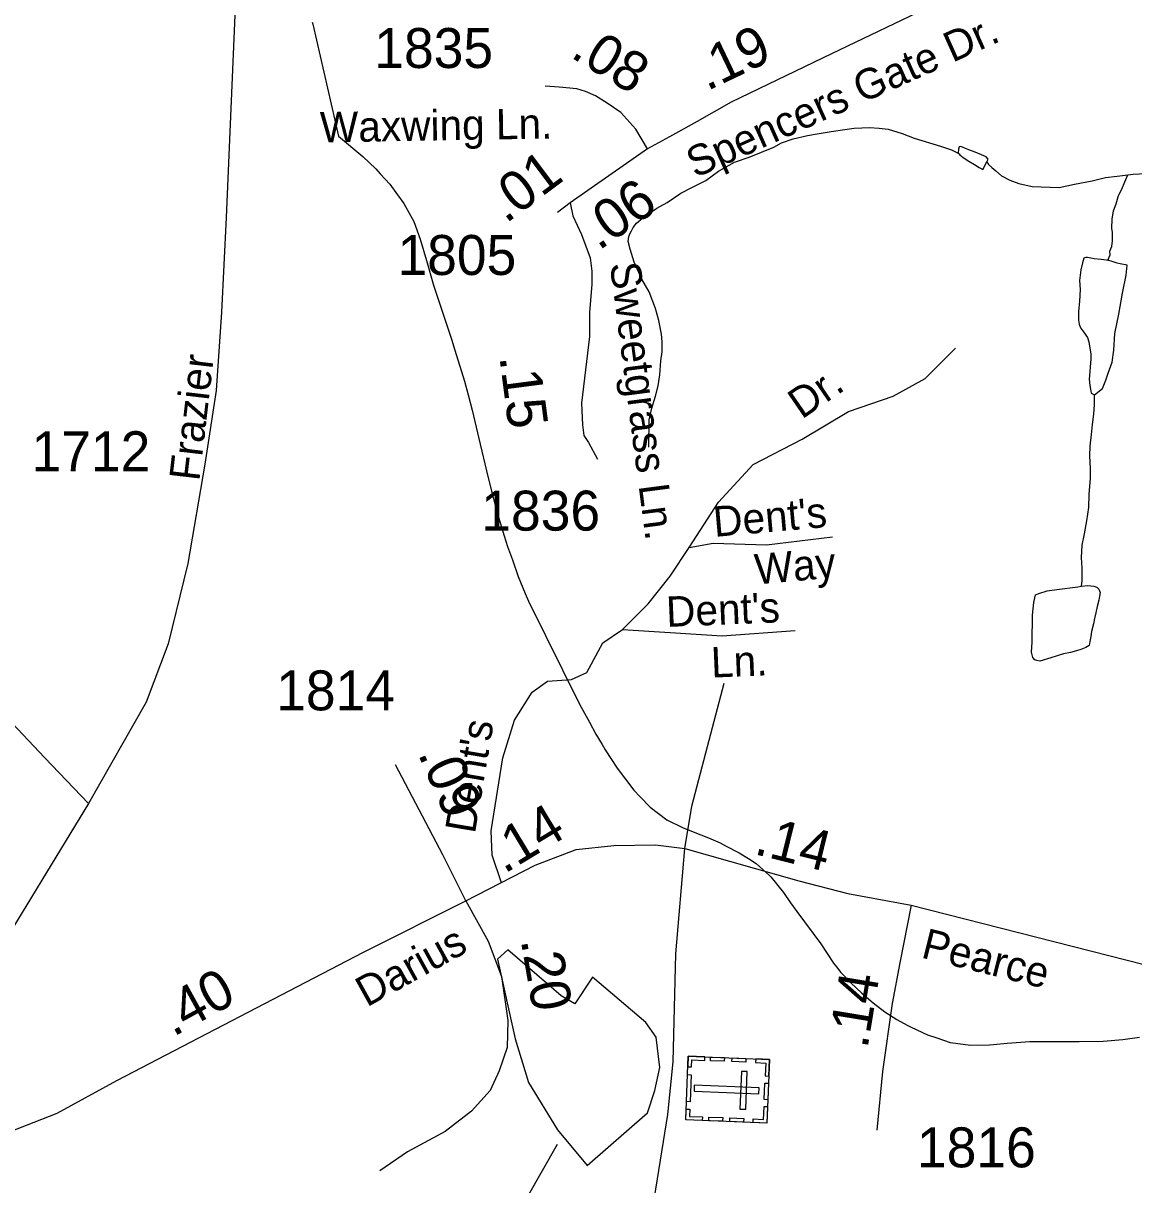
# Model space of a CAD drawing. Extents: x 2126262 to 2293712, y 749403 to 919119.
# Drawn here: x 2183876 to 2187352, y 801398 to 805032 of the extents above; entities that cross this region are included whole.
import ezdxf

# ---------------------------------------------------------------- set-up
doc = ezdxf.new("R2010")
doc.units = 0
for name, color, linetype in [('Exist Cultural Cemetery CELL', 7, 'Continuous'), ('Exist Hydrographic Misc Water Feature', 7, 'Continuous'), ('Exist Road Non-System Type 51', 7, 'Continuous'), ('Exist Road Non-System Type 51 Label', 7, 'Continuous'), ('Exist Road Secondary Mileage Hundredths English Label', 7, 'Continuous'), ('Exist Road Secondary Type 51 Attributed', 7, 'Continuous'), ('Exist Road Secondary Type 51 Label', 7, 'Continuous'), ('Exist Road Secondary Type 51 Number Label', 7, 'Continuous')]:
    doc.layers.add(name, color=color, linetype=linetype)

msp = doc.modelspace()

# ---------------------------------------------------------------- linework, layer by layer
at = {"layer": 'Exist Cultural Cemetery CELL'}
for points in [[(2186212.1, 801789.6), (2186203.9, 801590.6), (2185949.5, 801601.1), (2185957.7, 801800.1)], [(2185956.4, 801767), (2185967.9, 801766.5), (2185968.8, 801788.5), (2186009.1, 801786.9), (2186009.6, 801798), (2185957.7, 801800.1)], [(2186027.6, 801797.2), (2186070.9, 801795.4), (2186070.4, 801784), (2186027.1, 801785.8)], [(2186094.7, 801794.4), (2186138, 801792.6), (2186137.5, 801781.3), (2186094.3, 801783)], [(2186168.8, 801791.3), (2186168.4, 801780), (2186200.5, 801778.7), (2186198.8, 801738.2), (2186210, 801737.7), (2186212.1, 801789.6)], [(2186142.4, 801751.6), (2186123.8, 801752.4), (2186118.9, 801634.7), (2186137.6, 801633.9)], [(2185966.8, 801742.2), (2185963.3, 801657.4), (2185951.9, 801657.9), (2185955.4, 801742.6)], [(2186209, 801715.6), (2186206.9, 801663.8), (2186195.5, 801664.2), (2186197.6, 801716)], [(2186178.3, 801681.8), (2186179.1, 801700.5), (2185976.5, 801708.9), (2185975.7, 801690.2)], [(2186160.6, 801592.4), (2186161, 801603.7), (2186193.2, 801602.4), (2186194.9, 801642.9), (2186206, 801642.4), (2186203.8, 801590.6)], [(2185950.9, 801634.2), (2185962.3, 801633.8), (2185961.4, 801611.8), (2186001.8, 801610.1), (2186001.3, 801599), (2185949.5, 801601.1)], [(2186022.2, 801609.5), (2186065.4, 801607.7), (2186065, 801596.4), (2186021.7, 801598.1)], [(2186088, 801606.8), (2186131.3, 801605), (2186130.8, 801593.6), (2186087.6, 801595.4)]]:
    msp.add_lwpolyline(points, close=True, dxfattribs=at)
at = {"layer": 'Exist Hydrographic Misc Water Feature'}
for p, q in [((2184780.9, 805035), (2184782.2, 805029.1)), ((2185216.1, 804043.7), (2185227.3, 804009.3)), ((2186211.6, 802365.4), (2186216.3, 802361.2)), ((2186900.2, 801835.5), (2186912.5, 801836.7)), ((2187318, 801852.2), (2187370.1, 801859.2))]:
    msp.add_line(p, q, dxfattribs=at)
for points in [[(2184782.2, 805029.1), (2184863.2, 804678.3), (2184939.2, 804615.3), (2184979.2, 804576.3), (2184993.6, 804560.6)], [(2184782.2, 805029.1), (2184863.2, 804678.3), (2184939.2, 804615.3), (2184979.2, 804576.3), (2184993.6, 804560.6)], [(2185834.3, 803705.4), (2185834.1, 803733.4), (2185835.7, 803767.4), (2185835.7, 803791.4), (2185843.5, 803827.5), (2185855.2, 803865.5), (2185863, 803897.5), (2185868.7, 803931.6), (2185872.2, 803975.6), (2185876.3, 804003.6), (2185875.9, 804035.6), (2185873.7, 804059.6), (2185865.5, 804101.5), (2185855.2, 804139.4), (2185834.9, 804191.3), (2185812.6, 804231.1), (2185788.4, 804284.9), (2185776.1, 804324.8), (2185769.7, 804348.8), (2185771.8, 804364.8), (2185775.9, 804374.8), (2185779.5, 804382.9), (2185785.5, 804392.9), (2185795.5, 804406.9), (2185815.2, 804423.1), (2185835.3, 804437.2), (2185859.1, 804453.4), (2185891.1, 804471.6), (2185934.8, 804499.9), (2185968.6, 804518.1), (2186012.5, 804540.4), (2186052.3, 804568.7), (2186102.1, 804597), (2186148, 804613.3), (2186225.7, 804643.8), (2186249.5, 804658), (2186285.6, 804670.3), (2186331.3, 804680.6), (2186367.2, 804686.8), (2186405.4, 804693.1), (2186447.2, 804699.4), (2186477.3, 804703.6), (2186525.3, 804705.9), (2186555.3, 804704), (2186583.3, 804700.3), (2186627.2, 804686.6), (2186665.2, 804672.9), (2186747.6, 804647.4), (2186781.4, 804635.7), (2186802.3, 804625.3), (2186805.4, 804623.8)], [(2186891.7, 804598.4), (2186893.8, 804602.4), (2186895.8, 804606.4), (2186889.7, 804614.4), (2186875.5, 804620.3), (2186855.5, 804628.2), (2186835.6, 804636.1), (2186825.5, 804640), (2186815.5, 804643.9), (2186809.5, 804645.9), (2186805.4, 804645.8), (2186803.6, 804637.8), (2186802.3, 804625.3), (2186805.4, 804623.8)], [(2186805.4, 804623.8), (2186807.7, 804619.9), (2186817.7, 804611.9), (2186835.8, 804600.1), (2186853.8, 804590.2), (2186868, 804580.3), (2186876, 804576.3), (2186880.1, 804574.4), (2186891.7, 804598.4)], [(2186891.7, 804598.4), (2186897.7, 804590.5), (2186907.7, 804580.5), (2186920, 804570.6), (2186938.1, 804554.8), (2186963.9, 804540.9), (2186992.2, 804531.1), (2187034.3, 804521.4), (2187118.3, 804518), (2187166.3, 804528.4), (2187222.1, 804538.8), (2187263.9, 804549), (2187300, 804553.3), (2187334, 804557.5)], [(2184993.6, 804560.6), (2185023.3, 804528.1), (2185047.5, 804495.1)], [(2184993.6, 804560.6), (2185023.3, 804528.1), (2185047.5, 804495.1)], [(2187273.8, 804289.2), (2187271.7, 804293.1), (2187277.9, 804307.2), (2187277.4, 804319.2), (2187283.6, 804333.3), (2187285.2, 804351.2), (2187285.2, 804377.2), (2187283, 804391.2), (2187284.8, 804419.2), (2187288.7, 804445.3), (2187296.5, 804467.3), (2187304.3, 804493.3), (2187314.4, 804513.4), (2187324, 804535.4), (2187334, 804557.5)], [(2187334, 804557.5), (2187349.8, 804559.6), (2187389.8, 804561.9)], [(2185047.5, 804495.1), (2185067, 804468.4), (2185098.4, 804411.4), (2185118.3, 804356.7), (2185137.9, 804289.4)], [(2185047.5, 804495.1), (2185067, 804468.4), (2185098.4, 804411.4), (2185118.3, 804356.7), (2185137.9, 804289.4)], [(2187273.8, 804289.2), (2187249.8, 804293), (2187227.8, 804294.9), (2187207.7, 804298.7), (2187201.8, 804298.7), (2187195.8, 804296.6), (2187191.7, 804282.6), (2187186, 804260.6), (2187182.3, 804226.6), (2187184.6, 804198.5), (2187182.7, 804162.5), (2187179, 804128.6), (2187179, 804102.6), (2187181.3, 804090.6), (2187185.2, 804078.6), (2187195.2, 804066.7), (2187207.5, 804048.8), (2187211.4, 804034.8), (2187217.8, 803996.9), (2187218, 803980.9), (2187215.9, 803956.9), (2187214.3, 803942.9), (2187212.2, 803918.8), (2187214.5, 803898.8), (2187216.5, 803886.9), (2187218.8, 803874.9), (2187228.9, 803869)], [(2185137.9, 804289.4), (2185160.3, 804212.1), (2185216.1, 804043.7)], [(2185137.9, 804289.4), (2185160.3, 804212.1), (2185216.1, 804043.7)], [(2187228.9, 803869), (2187254.5, 803889.2), (2187264.3, 803915.3), (2187272.3, 803937.2), (2187284, 803971.4), (2187289.8, 804009.4), (2187293.2, 804061.4), (2187304.9, 804121.4), (2187316.4, 804187.5), (2187328.1, 804243.5), (2187331.8, 804275.6), (2187309.8, 804279.4), (2187299.8, 804281.4), (2187281.8, 804287.3), (2187273.8, 804289.2)], [(2185227.3, 804009.3), (2185257.5, 803911.8), (2185268.8, 803868.9)], [(2185227.3, 804009.3), (2185257.5, 803911.8), (2185268.8, 803868.9)], [(2185268.8, 803868.9), (2185281.3, 803821.9), (2185306.1, 803714.5)], [(2185268.8, 803868.9), (2185281.3, 803821.9), (2185306.1, 803714.5)], [(2187188.7, 803270.9), (2187190.7, 803288.9), (2187190.5, 803326.9), (2187188.3, 803360.8), (2187190.1, 803398.9), (2187197.7, 803434.9), (2187205.5, 803474.9), (2187211, 803517), (2187212.7, 803557), (2187216.5, 803609), (2187216.3, 803639), (2187214.1, 803678.9), (2187215.7, 803708.9), (2187219.4, 803745), (2187223.3, 803777), (2187227, 803809), (2187228.9, 803839), (2187228.9, 803869)], [(2185306.1, 803714.5), (2185325.6, 803631.4), (2185338.5, 803580.6)], [(2185306.1, 803714.5), (2185325.6, 803631.4), (2185338.5, 803580.6)], [(2185338.5, 803580.6), (2185357.3, 803507.7), (2185381.7, 803428.5)], [(2185338.5, 803580.6), (2185357.3, 803507.7), (2185381.7, 803428.5)], [(2185381.7, 803428.5), (2185392.2, 803394.4), (2185407, 803352.9)], [(2185381.7, 803428.5), (2185392.2, 803394.4), (2185407, 803352.9)], [(2185407, 803352.9), (2185425.2, 803301.1), (2185447.4, 803247.4)], [(2185407, 803352.9), (2185425.2, 803301.1), (2185447.4, 803247.4)], [(2185447.4, 803247.4), (2185457.2, 803223.7), (2185617.3, 802901.5), (2185648.1, 802845)], [(2185447.4, 803247.4), (2185457.2, 803223.7), (2185617.3, 802901.5), (2185648.1, 802845)], [(2187188.7, 803270.9), (2187208.8, 803273), (2187226.8, 803271.2), (2187236.8, 803267.2), (2187242.8, 803261.3), (2187247.1, 803251.3), (2187245.1, 803239.3), (2187243, 803227.3), (2187237.3, 803207.2), (2187233.2, 803187.2), (2187229.5, 803169.2), (2187225.6, 803153.2), (2187219.8, 803129.2), (2187217.8, 803113.1), (2187214.1, 803097.1), (2187212, 803085.1), (2187202, 803079.1), (2187186.2, 803072.9), (2187172.3, 803068.8), (2187154.2, 803062.8), (2187132.3, 803058.6), (2187092.3, 803046.3), (2187058.5, 803036), (2187048.4, 803038), (2187042.5, 803040), (2187036.5, 803047.9), (2187032.2, 803063.8), (2187034.1, 803095.9), (2187035.5, 803179.8), (2187039.2, 803219.9), (2187044.9, 803243.9), (2187055, 803248), (2187081, 803256.2), (2187110.9, 803260.4), (2187176.8, 803268.8), (2187188.7, 803270.9)], [(2185648.1, 802845), (2185668.2, 802808), (2185687.7, 802775.2)], [(2185648.1, 802845), (2185668.2, 802808), (2185687.7, 802775.2)], [(2185687.7, 802775.2), (2185697.3, 802758.9), (2185735.3, 802701.4)], [(2185687.7, 802775.2), (2185697.3, 802758.9), (2185735.3, 802701.4)], [(2185735.3, 802701.4), (2185787.3, 802632.6), (2185806.8, 802611.9)], [(2185735.3, 802701.4), (2185787.3, 802632.6), (2185806.8, 802611.9)], [(2185806.8, 802611.9), (2185838.2, 802579), (2185890.3, 802539.5), (2185941.5, 802514.1)], [(2185806.8, 802611.9), (2185838.2, 802579), (2185890.3, 802539.5), (2185941.5, 802514.1)], [(2185941.5, 802514.1), (2185997.3, 802492.9), (2186020.5, 802482.9)], [(2185941.5, 802514.1), (2185997.3, 802492.9), (2186020.5, 802482.9)], [(2186020.5, 802482.9), (2186057.2, 802467.2), (2186074.6, 802458.3)], [(2186020.5, 802482.9), (2186057.2, 802467.2), (2186074.6, 802458.3)], [(2186074.6, 802458.3), (2186117.3, 802436.8), (2186145.8, 802418.8)], [(2186074.6, 802458.3), (2186117.3, 802436.8), (2186145.8, 802418.8)], [(2186145.8, 802418.8), (2186170.2, 802403.3), (2186211.6, 802365.4)], [(2186145.8, 802418.8), (2186170.2, 802403.3), (2186211.6, 802365.4)], [(2186216.3, 802361.2), (2186255.3, 802312.3), (2186278, 802280.1)], [(2186216.3, 802361.2), (2186255.3, 802312.3), (2186278, 802280.1)], [(2186278, 802280.1), (2186297.3, 802252.8), (2186372.1, 802151.5)], [(2186278, 802280.1), (2186297.3, 802252.8), (2186372.1, 802151.5)], [(2186372.1, 802151.5), (2186412.3, 802091.4), (2186421.4, 802079.8)], [(2186372.1, 802151.5), (2186412.3, 802091.4), (2186421.4, 802079.8)], [(2186421.4, 802079.8), (2186435.3, 802062), (2186466.3, 802029.7)], [(2186421.4, 802079.8), (2186435.3, 802062), (2186466.3, 802029.7)], [(2186466.3, 802029.7), (2186501.3, 801997.2), (2186536.2, 801967.2), (2186573.1, 801938.9)], [(2186466.3, 802029.7), (2186501.3, 801997.2), (2186536.2, 801967.2), (2186573.1, 801938.9)], [(2186573.1, 801938.9), (2186610.2, 801914.6), (2186642.6, 801897.2)], [(2186573.1, 801938.9), (2186610.2, 801914.6), (2186642.6, 801897.2)], [(2186642.6, 801897.2), (2186653.3, 801891.5), (2186672.8, 801882.6)], [(2186642.6, 801897.2), (2186653.3, 801891.5), (2186672.8, 801882.6)], [(2186672.8, 801882.6), (2186706.2, 801867.2), (2186735.7, 801857.2)], [(2186672.8, 801882.6), (2186706.2, 801867.2), (2186735.7, 801857.2)], [(2186735.7, 801857.2), (2186777.3, 801843.3), (2186818.1, 801837.7)], [(2186735.7, 801857.2), (2186777.3, 801843.3), (2186818.1, 801837.7)], [(2186818.1, 801837.7), (2186841.3, 801834.6), (2186900.2, 801835.5)], [(2186818.1, 801837.7), (2186841.3, 801834.6), (2186900.2, 801835.5)], [(2186912.5, 801836.7), (2186956.3, 801841.2), (2187026.3, 801845.6), (2187081.2, 801845.5)], [(2186912.5, 801836.7), (2186956.3, 801841.2), (2187026.3, 801845.6), (2187081.2, 801845.5)], [(2187081.2, 801845.5), (2187181.3, 801845.5), (2187256.3, 801847.1), (2187318, 801852.2)], [(2187081.2, 801845.5), (2187181.3, 801845.5), (2187256.3, 801847.1), (2187318, 801852.2)], [(2185075.6, 800976.6), (2185240.5, 801071.9), (2185356.5, 801187.6), (2185548.8, 801525)]]:
    msp.add_lwpolyline(points, dxfattribs=at)
msp.add_lwpolyline([(2185392.6, 802132.3), (2185360.4, 802103.9), (2185415.3, 801854), (2185457, 801717.6), (2185547.9, 801569.9), (2185640.7, 801458.2), (2185830.2, 801622.9), (2185852.9, 801693), (2185868.1, 801765), (2185856.7, 801859.7), (2185824.5, 801905.1), (2185657.8, 802047.1), (2185602.9, 801963.8), (2185559.3, 801988.4), (2185513.8, 802028.2)], close=True, dxfattribs=at)
at = {"layer": 'Exist Road Non-System Type 51'}
for points in [[(2185960, 803391.5), (2186052.1, 803533.9), (2186161, 803651.2), (2186314, 803730.6), (2186459.1, 803817.2), (2186598.6, 803864.7), (2186699.1, 803920.5), (2186794, 804015.5)], [(2184080.5, 802590.6), (2183943, 802734.4), (2183825.1, 802859.4), (2183748.3, 802950.1), (2183721.8, 803109.3), (2183695.3, 803248), (2183694, 803299.7), (2183707.9, 803359.8), (2183706.5, 803587.4)], [(2185960, 803391.5), (2186035.4, 803405.4), (2186202.8, 803399.8), (2186409.4, 803425)], [(2185751.3, 803135), (2185831.7, 803215.5), (2185901.4, 803302.1), (2185960, 803391.5)], [(2185372.8, 802342.5), (2185343.9, 802429.3), (2185341.1, 802504.7), (2185377.4, 802733.8), (2185413.7, 802851.1), (2185469.4, 802939.5), (2185516.8, 802973), (2185592.2, 802978.6), (2185639.6, 803000.9), (2185689.9, 803093.1), (2185751.3, 803135)], [(2185751.3, 803135), (2185901.4, 803126.1), (2186063.3, 803114.9), (2186292.1, 803131.7)], [(2185946.6, 802449.5), (2185969, 802581.9), (2186022.7, 802789.3), (2186070.1, 802967.3)]]:
    msp.add_lwpolyline(points, dxfattribs=at)
at = {"layer": 'Exist Road Secondary Type 51 Attributed'}
for p, q in [((2185830, 804638.9), (2185588, 804470.2)), ((2185588, 804470.2), (2185547.8, 804440.1))]:
    msp.add_line(p, q, dxfattribs=at)
for points in [[(2184509.5, 809741.8), (2184539.5, 809475.8), (2184568.1, 809045), (2184583.4, 808828.5), (2184574.3, 808470.3), (2184552.7, 808121.9), (2184528.3, 807619.8), (2184505.3, 807129), (2184503.2, 806773.5), (2184516.4, 806293.8), (2184527.6, 805898.6), (2184547.2, 805335.8), (2184541.6, 805131.9), (2184511.1, 804424.6), (2184497.1, 804128.5), (2184480.4, 803882.7), (2184444.3, 803652), (2184391.3, 803341.9), (2184329.9, 803090.6), (2184260.5, 802907.6), (2184080.5, 802590.6), (2183769.5, 802082), (2183572.6, 801716.6)], [(2186723.7, 805088.8), (2186406.4, 804936.2), (2186091.6, 804785.6), (2185985.7, 804724.3), (2185899.3, 804677.1), (2185830, 804638.9)], [(2185830, 804638.9), (2185793.9, 804700.2), (2185746.7, 804752.4), (2185703.5, 804782.5), (2185667.3, 804804.6), (2185636.2, 804818.7), (2185609.1, 804826.7), (2185553.9, 804831.7), (2185509.7, 804834.8)], [(2185588, 804470.2), (2185596, 804429.1), (2185623.1, 804370.8), (2185650.3, 804298.5), (2185655.8, 804256.4), (2185655.8, 804215.2), (2185648.8, 804126.8), (2185648.3, 804051.5), (2185623.1, 803843.6), (2185626.2, 803775.4), (2185631.2, 803742.2), (2185645.2, 803720.1), (2185673.4, 803667.9)], [(2185261.1, 802286.2), (2185189.4, 802429.6), (2185040.9, 802711.2)], [(2185261.1, 802286.2), (2185478.7, 802398), (2185607.1, 802446.9), (2185724.3, 802459.4), (2185855, 802461.5), (2185946.6, 802449.5)], [(2185801.3, 801039.4), (2185893.8, 801618), (2185910.6, 801782.8), (2185918.9, 802120.8), (2185946.6, 802449.5)], [(2185946.6, 802449.5), (2186303.2, 802349), (2186456.8, 802308.9), (2186655.1, 802272.2)], [(2183506.1, 801450.3), (2183759.5, 801534.8), (2183982.3, 801621.9), (2184169.2, 801724.2), (2184940.8, 802125), (2185261.1, 802286.2)], [(2185261.1, 802286.2), (2185331.5, 802159.5), (2185372.5, 802049.4), (2185392.9, 801911.2), (2185390.4, 801826.7), (2185366.1, 801753.7), (2185337.9, 801692.3), (2185279, 801628.3), (2185197.1, 801564.3), (2185079.3, 801500.3), (2184992.3, 801441.4)], [(2186655.1, 802272.2), (2186620.2, 802092.4), (2186596.2, 801964.9), (2186565.5, 801752.4), (2186547.6, 801568.1)], [(2186655.1, 802272.2), (2187667.7, 802014.9), (2187792.1, 801990.1), (2188124.2, 801973.3), (2188428.4, 801951), (2188727, 801906.3), (2188934.9, 801854.6), (2189194.5, 801751.2), (2189423.3, 801661.9), (2189635.4, 801594.8), (2189943.8, 801540.4), (2190185.2, 801522.3)]]:
    msp.add_lwpolyline(points, dxfattribs=at)

# ---------------------------------------------------------------- texts
at = {"layer": 'Exist Road Non-System Type 51 Label'}
for s, rotation, p in [('Dr.', 34.4613, (2186312.8, 803791.3)), ("Dent's", 5.0771, (2186039.9, 803424.7)), ('Way', 5.0771, (2186169.5, 803275.8)), ("Dent's", 2.3883, (2185890.1, 803143)), ('Ln.', 2.3883, (2186030.6, 802984.5)), ("Dent's", 80.3999, (2185289.6, 802493.7))]:
    msp.add_text(s, height=95, rotation=rotation, dxfattribs=at).set_placement(p)
at = {"layer": 'Exist Road Secondary Mileage Hundredths English Label'}
for s, rotation, p in [('.08', 328.5704, (2185585.3, 804928)), ('.19', 25.5697, (2186016.4, 804818.9)), ('.01', 36.8699, (2185386.7, 804403.5)), ('.06', 34.8802, (2185677.4, 804319)), ('.15', 277.4606, (2185366.2, 803988.4)), ('.09', 293.6524, (2185110.2, 802746.9)), ('.14', 31.1291, (2185381.5, 802369.3)), ('.14', 346.1062, (2186160.4, 802433.2)), ('.20', 279.8388, (2185432.9, 802163.2)), ('.40', 28.8978, (2184345.4, 801859.4)), ('.14', 80.6765, (2186518.4, 801821))]:
    msp.add_text(s, height=125, rotation=rotation, dxfattribs=at).set_placement(p)
at = {"layer": 'Exist Road Secondary Type 51 Label'}
for s, rotation, p in [('Spencers Gate Dr.', 24.1604, (2185979.1, 804546.7)), ('Waxwing Ln.', 0.9978, (2184805.7, 804658.9)), ('Sweetgrass Ln.', 277.405, (2185711.9, 804279)), ('Frazier', 83.341, (2184427, 803597.4)), ('Pearce', 345.8715, (2186683.1, 802109.3)), ('Darius', 28.9434, (2184951.3, 801952.1))]:
    msp.add_text(s, height=95, rotation=rotation, dxfattribs=at).set_placement(p)
at = {"layer": 'Exist Road Secondary Type 51 Number Label'}
for s, p in [('1835', (2184974.9, 804892)), ('1805', (2185047.4, 804244.4)), ('1712', (2183902, 803630.3)), ('1836', (2185309.8, 803444.5)), ('1814', (2184667.8, 802882.1)), ('1816', (2186673.5, 801452.2))]:
    msp.add_text(s, height=125, dxfattribs=at).set_placement(p)

doc.saveas('drawing.dxf')
